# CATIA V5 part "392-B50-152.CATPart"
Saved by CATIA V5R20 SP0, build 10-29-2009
Part number: 392-B50-152
Definition: NONE
Nomenclature: 392-B50-152
Source: Unknown
Description: 392-B50-152
Bounding box of the stored display mesh (mm): x 0 to 152, y -24.567 to 24.567, z -24.4 to 24.222
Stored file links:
  C:\Users\Utente\Desktop\IO LAVORO\3D X SITO CF\X SITO\3D files 392B\392-B50-152.CATPart
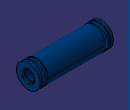
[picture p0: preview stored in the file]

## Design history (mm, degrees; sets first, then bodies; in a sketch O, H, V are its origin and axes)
Body1 "392-B50-152" (main body)
  Solid1: solid without history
